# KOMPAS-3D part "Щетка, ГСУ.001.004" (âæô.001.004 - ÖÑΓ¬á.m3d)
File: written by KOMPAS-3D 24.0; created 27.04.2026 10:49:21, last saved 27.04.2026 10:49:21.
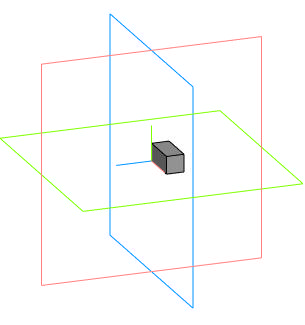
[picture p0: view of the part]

Document properties: Автор: User7; Полное имя файла: C:\Users\User7\Desktop\Двигатель мясорубки\ГСУ.001.004 - Щетка.m3d

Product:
- Part/product: Щетка  | designation ГСУ.001.004
    Масса: 0.001131

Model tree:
1. Эскиз:1
2. Элемент выдавливания:1
     Расстояние 1 = 9

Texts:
  ГСУ.001.004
